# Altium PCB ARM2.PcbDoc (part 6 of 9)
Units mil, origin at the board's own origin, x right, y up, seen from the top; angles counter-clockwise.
Board outline 4700.79 x 3937.01 mil, 6 copper layers (Top Layer, GND02, ART03, ART04, PWR05, Bottom Layer); 697 components, 508 nets, 2326 pads, 1231 vias.
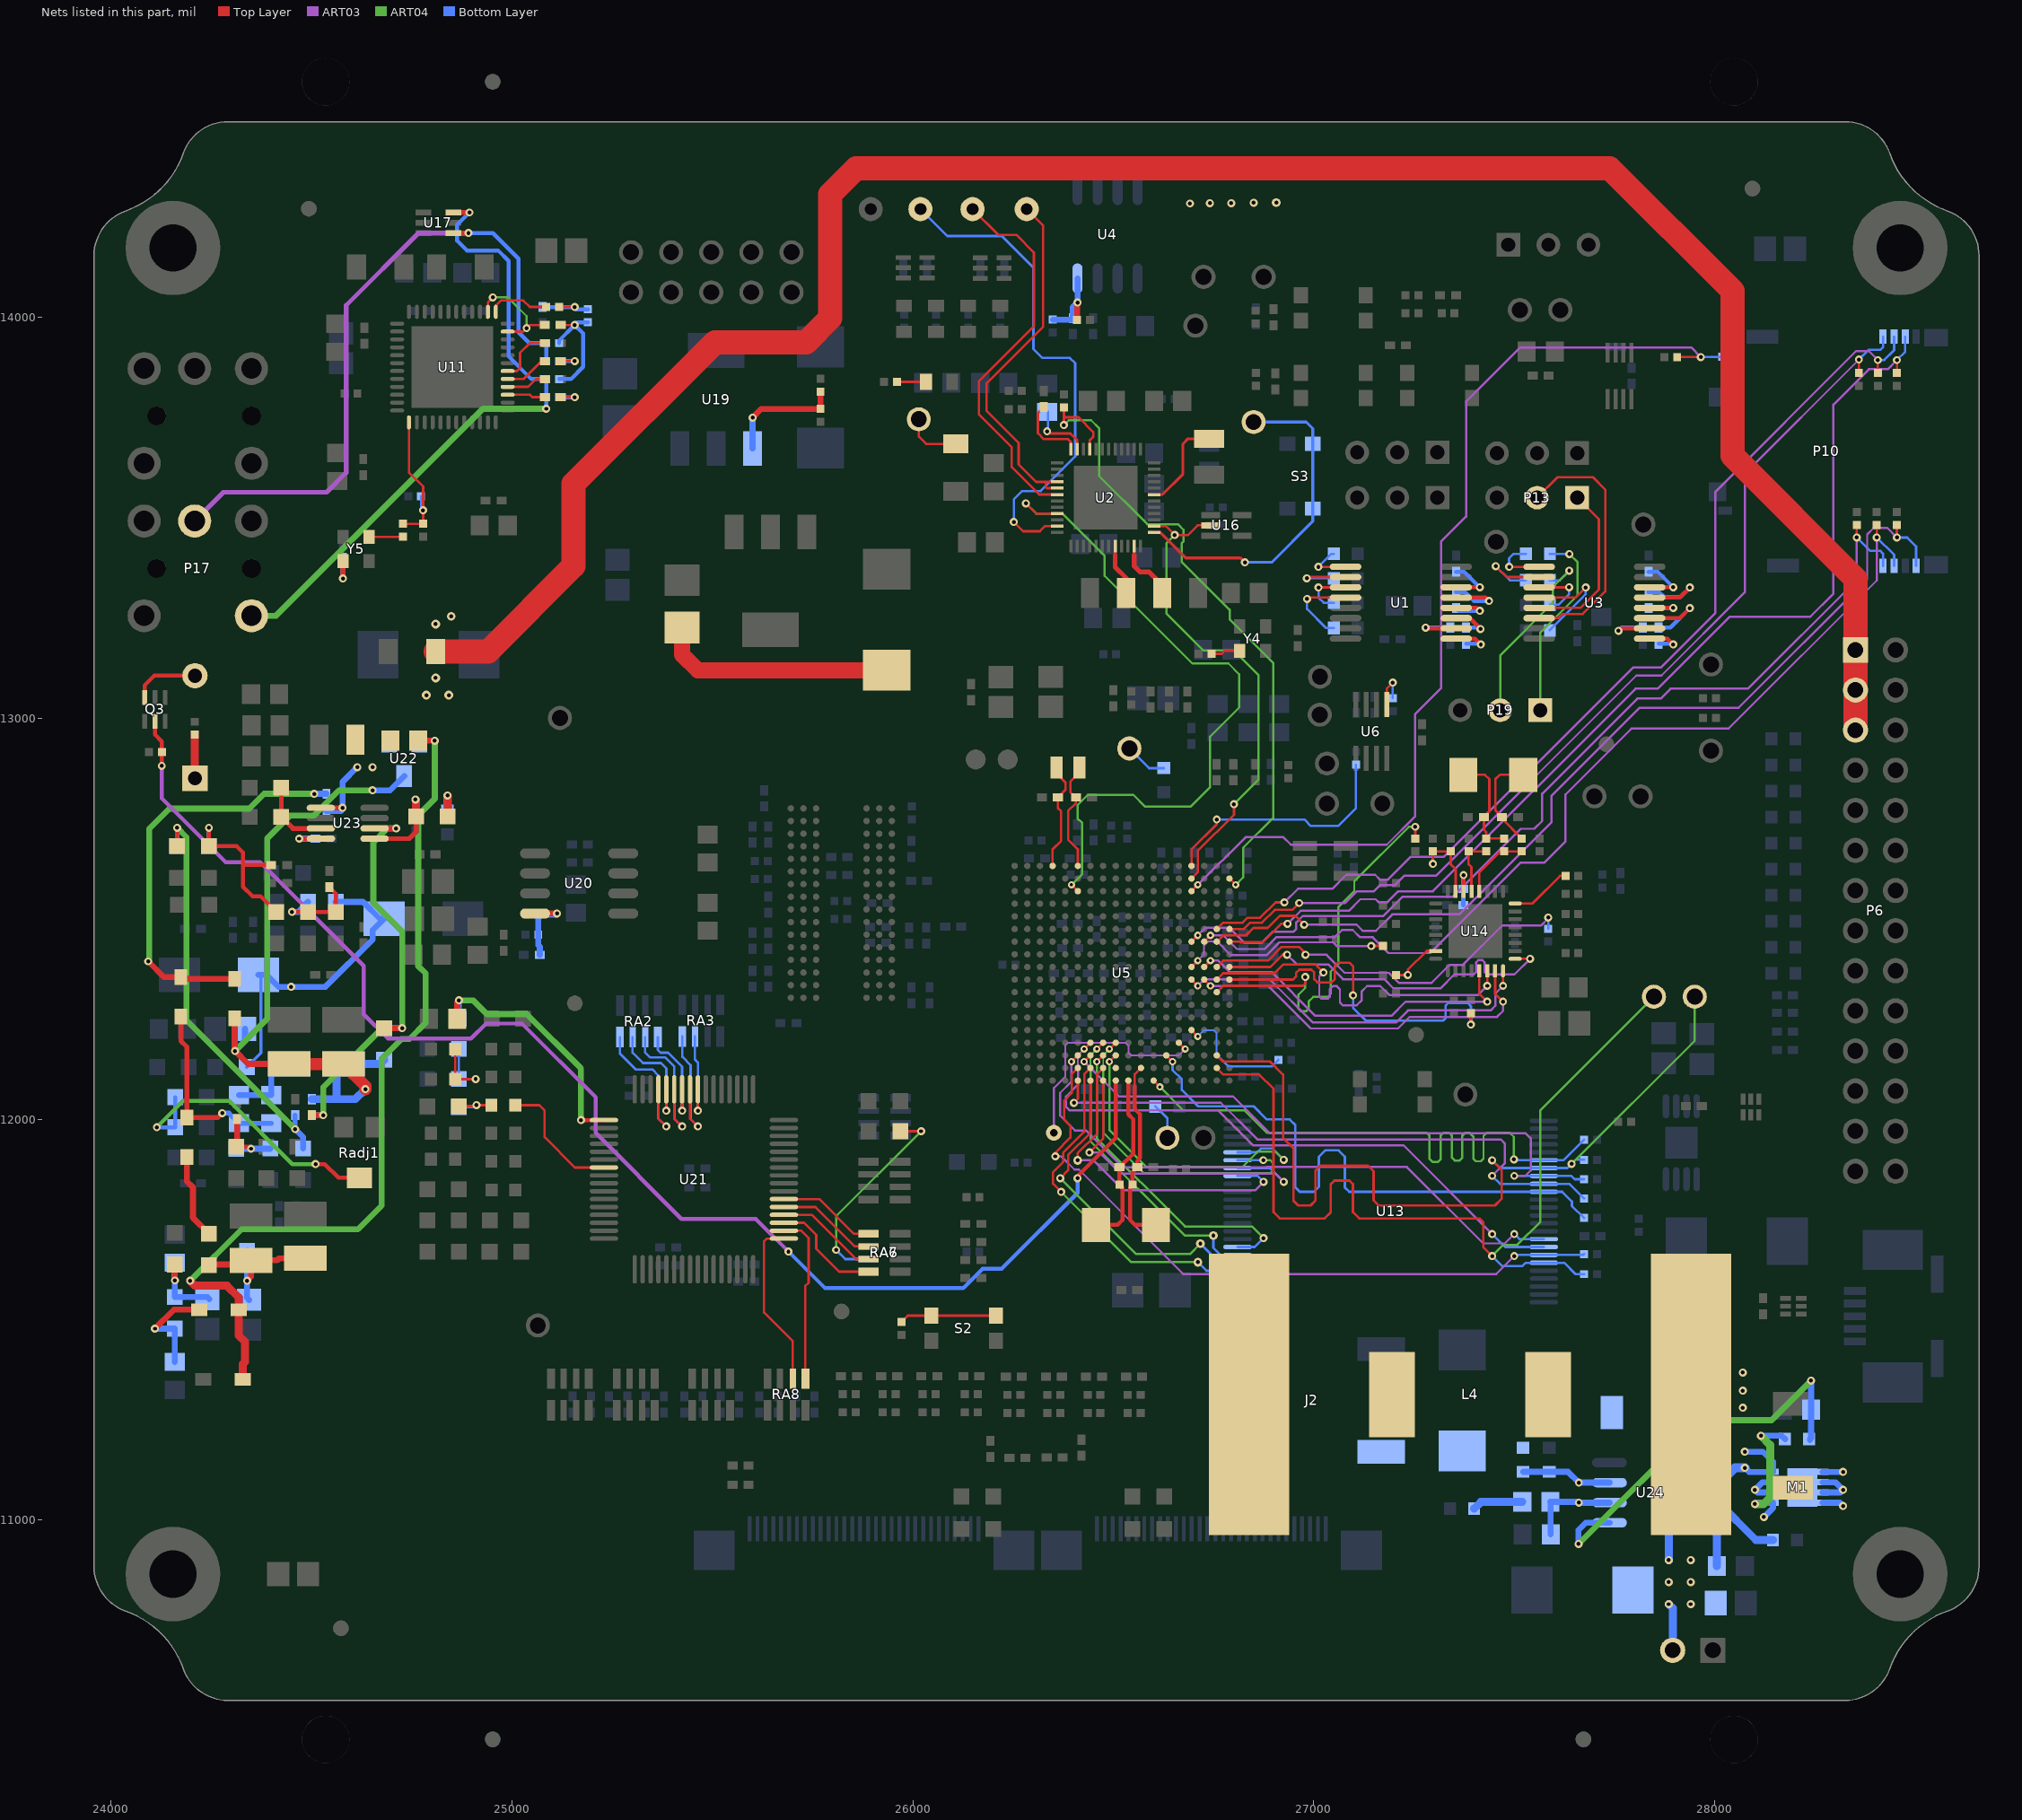
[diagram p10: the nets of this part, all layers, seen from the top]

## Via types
v1: diameter 20, hole 10, Top Layer to Bottom Layer, tented both sides, 871 vias
v2: diameter 18, hole 8, Top Layer to Bottom Layer, tented both sides, 273 vias
v3: diameter 22, hole 10, Top Layer to Bottom Layer, tented both sides, 64 vias
v4: diameter 20, hole 10, Top Layer to Bottom Layer, 18 vias
v5: diameter 22, hole 12, Top Layer to Bottom Layer, 4 vias
v6: diameter 39.37, hole 19.68, Top Layer to Bottom Layer, 1 vias

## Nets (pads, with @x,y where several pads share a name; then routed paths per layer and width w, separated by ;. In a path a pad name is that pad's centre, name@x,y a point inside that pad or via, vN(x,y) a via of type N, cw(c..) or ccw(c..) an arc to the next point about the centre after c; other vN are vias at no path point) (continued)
MII1_RXD3: R125.1 U5.L17 | length 986.3
  Top Layer w6: U5.L17@26758.2,12316.76 26773.94,12332.5 26972.88,12332.5 26979,12338.62 v1(26979,12354.73) ; R125.1@27253.11,12700.14 v1(27253.11,12729.32)
  ART04 w5.5: v1(26979,12354.73) 26979,12327.48 26961.79,12310.26 26961.79,12275.41 26967.58,12269.61 26981.66,12269.61 26987.16,12275.12 26987.16,12293.35 26998.82,12305.01 27034.82,12305.01 27042.34,12312.53 27042.34,12367.99 27061.12,12386.77 27061.12,12528.57 27101.12,12568.57 27101.12,12592.99 27237.46,12729.32 v1(27253.11,12729.32)
MII1_RXDV: R129.1 U5.J17 | length 983.4
  Top Layer w6: U5.J17@26758.2,12379.75 26773.94,12395.49 26885.87,12395.49 26920.05,12429.67 26963.33,12429.67 26979.26,12413.74 v1(26979.26,12410)
  ART03 w5.5: v1(26979.26,12410) 27032,12410 27077,12365 27187,12365 27212,12340 27294,12340 27339,12385 27372,12385 27469.7,12482.7 27566.7,12482.7 27585,12501 v1(27585,12503)
  Bottom Layer w6: R129.1@27585,12475.14 v1(27585,12503)
MII1_RXERR: R133.1 U5.J15 | length 547.3
  Top Layer w6: U5.J15@26695.21,12379.75 v2(26710.96,12395.5) ; v1(27143.54,12432) R133.1@27172.72,12432
  ART03 w4.4: v2(26710.96,12395.5) 26726.46,12411 26726.46,12432.92 26736.53,12442.99 26749.39,12442.99
  ART03 w5.5: 26749.39,12442.74 26759.4,12442.74 26792.81,12409.32 26882.69,12409.32 26914.47,12441.1 27048.15,12441.1 27057.25,12432 v1(27143.54,12432)
MII1_TXCLK: R134.1 U5.K18 | length 914.1
  Top Layer w6: U5.K18@26789.7,12348.25 26948.63,12348.25 26956,12355.62 26956,12364.57 26964.15,12372.73 26994.16,12372.73 27001,12365.89 27001,12349.28 27009.04,12341.25 27044.72,12341.25 27052.7,12349.23 27052.7,12382.63 27060.45,12390.37 27089.13,12390.37 27098,12381.5 v1(27098,12309) ; v1(27391.88,12236.06) R134.1@27391.88,12263.92
  Bottom Layer w6: v1(27098,12309) 27098,12277.67 27129.8,12245.87 27322.58,12245.87 27329,12252.29 27329,12283.55 27335.08,12289.63 27383.92,12289.63 27391.88,12281.67 v1(27391.88,12236.06)
MII1_TXD0: U5.K17 U14.22 | length 926.6
  Top Layer w6: U5.K17@26758.2,12348.25 26773.94,12363.99 26902.28,12363.99 26924.29,12386 27004,12386 v1(27024,12366) ; v1(27432.66,12332.56) U14.22@27432.66,12370
  ART03 w5.5: v1(27024,12366) 27013.85,12355.85 27013.85,12306.16 27019.61,12300.4 27034.66,12300.4 27039.75,12305.49 27039.75,12323.98 27047.4,12331.63 27057.6,12331.63 27065.25,12323.98 27065.25,12290.75 27072,12284 27107,12284 27120,12297 27120,12319 27133,12332 27166,12332 27188,12310 27410.1,12310 v1(27432.66,12332.56)
MII1_TXD1: U5.K16 U14.23 | length 922.1
  Top Layer w6: U5.K16@26726.7,12348.25 v2(26742.45,12332.51) ; U14.23@27452.36,12370 27452.36,12312.86 v1(27472.06,12293.16)
  ART03 w5.5: v2(26742.45,12332.51) 26886.49,12332.51 26992.71,12226.29 27210.29,12226.29 27239.24,12255.24 27457.3,12255.24 27472.06,12270 v1(27472.06,12293.16)
MII1_TXD2: U5.K15 U14.24 | length 928
  Top Layer w6: U5.K15@26695.21,12348.25 v2(26710.96,12332.51) ; v1(27472.06,12332.56) U14.24@27472.06,12370
  ART03 w5.5: v2(26710.96,12332.51) 26727.22,12348.78 26890.22,12348.78 26998,12241 27205,12241 27235.24,12271.24 27441.24,12271.24 27453,12283 27453,12313.5 v1(27472.06,12332.56)
MII1_TXD3: U5.J18 U14.25 | length 923.7
  Top Layer w6: U5.J18@26789.7,12379.75 26891.75,12379.75 26922,12410 v1(26933.72,12410) ; U14.25@27502.11,12400.05 v1(27539.55,12400.05)
  ART03 w5.5: v1(26933.72,12410) 26957.72,12386 27036,12386 27073,12349 27176,12349 27199,12326 27316,12326 27351,12361 27399.1,12361 27405.25,12367.15 27405.25,12391.26 27411.4,12397.41 27419.6,12397.41 27425.75,12391.26 27425.75,12367.15 27431.9,12361 27500.5,12361 v1(27539.55,12400.05)
MII1_TXEN: U5.J16 U14.21 | length 869
  Top Layer w6: U5.J16@26726.7,12379.75 v2(26742.45,12395.5) ; U14.21@27412.96,12370 27412.96,12312.86 v1(27432.66,12293.16)
  ART03 w5.5: v2(26742.45,12395.5) 26761.76,12395.5 26790.32,12366.94 26895.06,12366.94 27004,12258 27194,12258 27229.16,12293.16 v1(27432.66,12293.16)
MMC0_CD: P10.10 R157.1 U5.C15 | length 2508.7
  Top Layer w6: U5.C15@26695.21,12568.72 v2(26710.96,12584.47) ; R157.1@27906.27,13900.57 v1(27965.12,13900.57)
  ART03 w5.5: v2(26710.96,12584.47) 26829.88,12703.39 26924.31,12703.39 26943.12,12684.57 27182.12,12684.57 27253.12,12755.57 27253.12,13010.71 27318.12,13075.71 27318.12,13441.12 27380,13503 27380,13789.45 27515.12,13924.57 27941.12,13924.57 v1(27965.12,13900.57)
  Bottom Layer w6: v1(27965.12,13900.57) 28025.81,13900.57 P10.10@28026.37,13901.13
MMC0_CLKO: P10.5 R152.2 U5.G17 | length 2405.5
  Top Layer w6: U5.G17@26758.2,12442.74 26773.94,12458.48 26830.82,12458.48 26849.34,12477 26885.05,12477 26915.33,12507.28 26954.11,12507.28 v1(26976.14,12485.25) ; v1(28454.12,13450.57) R152.2@28454.12,13482.29
  ART03 w5.5: v1(26976.14,12485.25) 27106.45,12485.25 27122.12,12469.57 27155.12,12469.57 27196.12,12510.57 27363.01,12510.57 27592.56,12740.12 27592.56,12805.64 27813.12,13026.2 28059.58,13026.2 28380.12,13346.75 28380.12,13458.29 28396.41,13474.57 28430.12,13474.57 v1(28454.12,13450.57)
  Bottom Layer w6: v1(28454.12,13450.57) 28480.12,13450.57 28502.33,13428.37 P10.5@28502.33,13380.17
MMC0_CMD: P10.3 R151.2 U5.G18 | length 2644.9
  Top Layer w6: U5.G18@26789.7,12442.74 26815,12442.74 ; 26816.74,12441 26872.75,12441 26919.12,12487.37 v1(26934.78,12487.37) ; R151.2@28454.43,13861.42 v1(28454.43,13893.13)
  ART03 w5.5: v1(26934.78,12487.37) 26967.28,12519.87 27087.42,12519.87 27116.12,12548.57 27154.12,12548.57 27161.12,12541.57 27184.12,12541.57 27211.12,12568.57 27297.3,12568.57 27802.38,13073.66 27857.7,13073.66 28037.35,13253.3 28238.68,13253.3 28296.12,13310.75 28296.12,13781.91 28384.56,13870.35 28431.65,13870.35 v1(28454.43,13893.13)
  Bottom Layer w6: v1(28454.43,13893.13) 28474.76,13913.47 P10.3@28474.76,13951.61
MMC0_DAT0: P10.7 R153.2 U5.G16 | length 2422.1
  Top Layer w6: U5.G16@26726.7,12442.74 v2(26742.45,12458.49) ; v1(28404.12,13450.57) R153.2@28404.12,13482.29
  ART03 w5.5: v2(26742.45,12458.49) 26774.34,12458.49 26808.52,12424.31 26877.87,12424.31 26907.84,12454.28 27052.99,12454.28 27070.55,12471.84 27097.12,12471.84 27115.39,12453.57 27147.12,12453.57 27186.45,12414.25 27289.8,12414.25 27515.11,12639.56 27574.86,12639.56 27627.94,12692.64 27627.94,12809.84 27792.4,12974.3 28034.68,12974.3 28404.12,13343.75 v1(28404.12,13450.57)
  Bottom Layer w6: v1(28404.12,13450.57) 28447.21,13407.49 P10.7@28447.21,13380.17
MMC0_DAT1: P10.8 R154.2 U5.G15 | length 2362.7
  Top Layer w6: U5.G15@26695.21,12442.74 v2(26710.96,12458.49) ; v1(28354.12,13450.57) R154.2@28354.12,13482.29
  ART03 w5.5: v2(26710.96,12458.49) 26729.47,12477 26790.09,12477 26828.01,12439.08 26869.71,12439.08 26897.66,12467.04 26948.77,12467.04 26956.35,12474.62 26956.35,12490.56 26972.86,12507.07 27173.62,12507.07 27221.12,12554.57 27346.12,12554.57 27515.84,12724.29 27550.1,12724.29 27569.72,12743.91 27569.72,12811.75 27806.86,13048.89 27865.27,13048.89 27889.88,13073.5 28082.87,13073.5 28354.12,13344.75 v1(28354.12,13450.57)
  Bottom Layer w6: v1(28354.12,13450.57) 28387.12,13417.57 28412.12,13417.57 28419.65,13410.05 P10.8@28419.65,13380.17
MMC0_DAT2: P10.1 R150.2 U5.F18 | length 2463.3
  Top Layer w6: U5.F18@26789.7,12474.24 26825.81,12474.24 26841.56,12489.99 26870.99,12489.99 26902.96,12521.96 26946.73,12521.96 v1(26963.8,12539.03) ; R150.2@28359.43,13861.42 v1(28359.43,13894.27)
  ART03 w5.5: v1(26963.8,12539.03) 27078.58,12539.03 27108.12,12568.57 27150.12,12568.57 27165.12,12583.57 27202.12,12583.57 27226.12,12607.57 27305.55,12607.57 27804.31,13106.34 27867,13106.34 28074.8,13314.14 28074.8,13609.65 v1(28359.43,13894.27)
  Bottom Layer w6: v1(28359.43,13894.27) 28383.82,13918.67 28413.06,13918.67 28419.65,13925.25 P10.1@28419.65,13951.61
MMC0_DAT3: P10.2 R155.2 U5.F17 | length 2558.2
  Top Layer w6: U5.F17@26758.2,12474.24 26773.94,12489.98 26822.42,12489.98 26834.78,12502.34 26866.4,12502.34 26904.76,12540.7 v1(26926.77,12540.7) ; R155.2@28406.71,13861.42 v1(28406.71,13893.13)
  ART03 w5.5: v1(26926.77,12540.7) 26960.62,12574.55 27046.11,12574.55 27081.12,12609.57 27153.12,12609.57 27165.12,12597.57 27185.12,12597.57 27242.12,12654.57 27324.75,12654.57 27796.37,13126.19 27865.38,13126.19 28001.75,13262.56 28001.75,13564.68 28352.82,13915.75 28384.1,13915.75 v1(28406.71,13893.13)
  Bottom Layer w6: v1(28406.71,13893.13) 28422.65,13893.13 28447.21,13917.69 P10.2@28447.21,13951.61
MMC1_CLK: U5.U9
MMC1_CMD_BEEP: Q3.2 R34.1 U5.V9 | length 3561.1
  Top Layer w10: Q3.2@24110.19,12992.54 24110.19,12959.07 24127.33,12941.93 R34.1@24127.33,12915.07 v1(24127.33,12881.21) ; v1(26411,11852.62) 26411,11858.04 26506.23,11953.27 U5.V9@26506.23,12096.28
  ART03 w10: v1(24127.33,12881.21) 24127.33,12800.37 24286.7,12641 24372.7,12641 24631,12382.7 24631,12261.7 24691.7,12201 24898.55,12201 24936.12,12238.57 25025.43,12238.57 25209.12,12054.88 25209.12,11965.88 25423.43,11751.57 25608.43,11751.57 v1(25690,11670)
  Bottom Layer w10: v1(25690,11670) 25781.57,11578.43 26125.83,11578.43 26174.41,11627 26221.63,11627 26411,11816.37 v1(26411,11852.62)
MODE2: R113.1 R138.2 U14.15 | length 161
  Top Layer w6: R138.2@27205,12359.83 v1(27234.67,12359.83) 27234.67,12372.42 27282,12419.75 U14.15@27304.11,12419.75
  Bottom Layer w6: R113.1@27205,12359.83 v1(27234.67,12359.83)
NAND_ALE: U5.R7 U13.17 | length 1521.4
  Top Layer w6: v2(26427.49,12175.03) U5.R7@26443.24,12190.77
  ART03 w4.4: 26411.99,12136.59 26411.99,12159.53 v2(26427.49,12175.03)
  ART03 w5.5: 26411.99,12136.59 26411.99,12085.99 26382.48,12056.48 26382.48,12030.52 26391.42,12021.58 26762.06,12021.58 26848.61,11935.03 27223.59,11935.03 v1(27445,11713.62)
  Bottom Layer w6: v1(27445,11713.62) 27477.36,11681.26 U13.17@27573.78,11681.26
NAND_CLE: U5.T6 U13.16 | length 1522.2
  Top Layer w6: v2(26395.99,12143.54) U5.T6@26411.74,12159.28
  ART03 w5.5: v2(26395.99,12143.54) 26395.99,12093.99 26367.67,12065.67 26367.67,12008.79 26404.47,11972 26431.7,11972 26523.66,11880.04 26881.35,11880.04 26881.94,11880.62 27232.43,11880.62 27422.77,11690.28 27476.66,11690.28 v1(27500,11713.62)
  Bottom Layer w6: v1(27500,11713.62) 27512.69,11700.94 U13.16@27573.78,11700.94
NAND_CSN0: R29.1 U5.V6 U13.9 | length 1521.5
  Top Layer w6: v1(26402,12041) 26411.74,12050.74 U5.V6@26411.74,12096.28
  ART03 w5.5: v1(26402,12041) 26768.17,12041 26859.72,11949.45 27466.41,11949.45 27476.04,11939.82 27476.04,11889.66 v1(27445,11858.62)
  Bottom Layer w6: v1(27445,11858.62) 27464.88,11838.74 U13.9@27573.78,11838.74 27637.5,11838.74 R29.1@27673.86,11802.38
NAND_CSN3: R16.1 U5.T13 U13.10 | length 1509.7
  Top Layer w6: U5.T13@26632.22,12159.28 v2(26647.97,12143.54)
  Bottom Layer w6: v2(26647.97,12143.54) 26647.97,12122.66 26671,12099.62 26671,12072.62 26711.49,12032.14 26850.7,12032.14 26883.29,11999.54 26940.15,11999.54 26953.92,11985.77 26953.92,11830.3 26965.17,11819.05 27000.13,11819.05 27012.53,11831.45 27012.53,11906.12 27028.64,11922.23 27062.15,11922.23 27077.74,11906.63 27077.74,11829.6 27088.29,11819.05 U13.10@27573.78,11819.05 27619.58,11819.05 27644,11794.62 27644,11783.48 R16.1@27673.86,11753.62
NAND_D0: U5.U7 U13.29 | length 877.6
  Top Layer w6: v1(26369.89,11818.63) 26349.92,11838.6 26349.92,11867.93 26375.26,11893.26 26375.26,11915.94 26427.88,11968.57 26427.88,12112.42 U5.U7@26443.24,12127.78
  ART04 w5.5: v1(26369.89,11818.63) 26544.9,11643.62 v3(26711.17,11643.62)
  Bottom Layer w6: v3(26711.17,11643.62) 26732.59,11622.2 U13.29@26810,11622.2
NAND_D1: U5.V7 U13.30 | length 825.7
  Top Layer w6: v1(26368,11852.62) 26387.53,11872.15 26387.53,11910.2 26443.24,11965.92 U5.V7@26443.24,12096.28
  ART04 w5.5: v1(26368,11852.62) 26557,11663.62 26691.19,11663.62 v3(26717.28,11689.71)
  Bottom Layer w6: v3(26717.28,11689.71) 26765.1,11641.89 U13.30@26810,11641.89
NAND_D2: U5.R8 U13.31 | length 760.6
  Top Layer w6: v2(26458.99,12175.03) U5.R8@26474.74,12190.77
  ART04 w4.4: 26443.49,12129 26443.49,12159.53 v2(26458.99,12175.03)
  ART04 w5.5: 26443.49,12129 26443.49,11944.86 26678.37,11709.98 v3(26749.7,11709.98)
  Bottom Layer w6: v3(26749.7,11709.98) 26749.7,11679.47 26767.61,11661.57 U13.31@26810,11661.57
NAND_D3: U5.T8 U13.32 | length 806.7
  Top Layer w6: v2(26458.99,12143.54) U5.T8@26474.74,12159.28
  ART04 w5.5: v2(26458.99,12143.54) 26458.99,11952.37 26678.98,11732.38 26846.24,11732.38 v1(26875,11703.62)
  Bottom Layer w6: U13.32@26810,11681.26 26852.64,11681.26 v1(26875,11703.62)
NAND_D4: U5.U8 U13.41 | length 831.5
  Top Layer w6: v3(26411.06,11897.49) 26411.06,11915.22 26459.38,11963.55 26459.38,12112.42 U5.U8@26474.74,12127.78
  ART03 w5.5: v3(26411.06,11897.49) 26451.13,11897.49 26526,11822.62 26854,11822.62 v1(26875,11843.62)
  Bottom Layer w6: U13.41@26810,11858.42 26860.21,11858.42 v1(26875,11843.62)
NAND_D5: U5.V8 U13.42 | length 837.5
  Top Layer w6: v1(26440.56,11917.1) 26474.74,11951.29 U5.V8@26474.74,12096.28
  ART03 w5.5: v1(26440.56,11917.1) 26465.52,11917.1 26518,11864.62 26904,11864.62 v1(26925,11843.62)
  Bottom Layer w6: U13.42@26810,11878.11 26890.51,11878.11 v1(26925,11843.62)
NAND_D6: U5.R9 U13.43 | length 815.6
  Top Layer w6: v2(26490.48,12175.03) U5.R9@26506.23,12190.77
  ART04 w4.4: 26474.98,12133.62 26474.98,12159.53 v2(26490.48,12175.03)
  ART04 w5.5: 26474.98,12133.62 26474.98,11966.67 26576.71,11864.95 26891.62,11864.95 26898.24,11871.57 26898.24,11890.99 26891.44,11897.79 v1(26874,11897.79)
  Bottom Layer w6: U13.43@26810,11897.79 v1(26874,11897.79)
NAND_D7: U5.T9 U13.44 | length 819.8
  Top Layer w6: v2(26490.48,12143.54) U5.T9@26506.23,12159.28
  ART04 w5.5: v2(26490.48,12143.54) 26490.48,11973.4 26583.27,11880.61 26821.98,11880.61 26860,11918.62 26905,11918.62 v1(26925,11898.62)
  Bottom Layer w6: U13.44@26810,11917.48 26858.86,11917.48 26868,11926.62 26897,11926.62 v1(26925,11898.62)
NAND_OEN: R31.1 U5.T7 U13.8 | length 1518.7
  Top Layer w6: v2(26427.49,12143.54) U5.T7@26443.24,12159.28
  ART03 w5.5: v2(26427.49,12143.54) 26514.41,12056.62 26798.57,12056.62 26889.77,11965.42 27527.47,11965.42 27540.97,11951.92 27540.97,11872.18 27527.41,11858.62 v1(27500,11858.62)
  Bottom Layer w6: v1(27500,11858.62) 27500.21,11858.42 U13.8@27573.78,11858.42 27642.38,11858.42 27650.51,11850.29 R31.1@27673.86,11850.29
NAND_WAIT0: R13.1 TP15.1 U5.T17 U13.7 | length 2105.3
  Top Layer w6: U5.T17@26758.2,12159.28 26773.5,12143.98 26890.64,12143.98 26923.51,12111.12 26923.51,11953.67 26949.47,11927.71 26949.47,11796.8 26961.44,11784.84 26992.01,11784.84 27004.02,11796.85 27004.02,11871.66 27016.33,11883.97 27135.78,11883.97 27149.13,11870.62 27149.13,11797.58 27161.87,11784.84 27451.89,11784.84 27468.36,11801.31 27468.36,11874.26 v1(27445,11897.62)
  ART04 w5.5: v1(27643.12,11888.57) 27950.12,12195.57 TP15.1@27950.12,12305.57
  Bottom Layer w6: v1(27445,11897.62) 27464.51,11878.11 U13.7@27573.78,11878.11 27632.66,11878.11 v1(27643.12,11888.57) 27653.17,11898.62 R13.1@27673.86,11898.62
NAND_WAIT1: R15.1 U5.V12 U13.6 | length 1582.3
  Top Layer w6: U5.V12@26600.72,12096.28 v2(26616.47,12080.54)
  ART04 w5.5: v2(26616.47,12080.54) 26675.26,12021.75 26827.88,12021.75 26884,11965.62 27282.27,11965.62 27289.03,11958.87 27289.03,11901.01 27296.22,11893.82 27309.96,11893.82 27316.06,11899.92 27316.06,11958.65 27323.04,11965.62 27338.08,11965.62 27344.92,11958.79 27344.92,11903.62 27351.48,11897.06 27363.97,11897.06 27370.53,11903.62 27370.53,11958.96 27377.19,11965.62 27389.01,11965.62 27397.73,11956.91 27397.73,11902.04 27404.69,11895.08 27416.55,11895.08 27423.35,11901.88 27423.35,11958.17 27430.79,11965.62 27489.42,11965.62 27499,11956.05 v1(27499,11899.62)
  Bottom Layer w6: v1(27499,11899.62) 27500.83,11897.79 U13.6@27573.78,11897.79 27623.02,11897.79 R15.1@27673.86,11948.62
NAND_WEN: R30.1 U5.U6 U13.18 | length 1717.1
  Top Layer w6: v1(26355.43,11907.33) 26355.43,11916.51 26393.06,11954.14 26393.06,11983.41 26377.89,11998.57 26377.89,12046.34 26396.38,12064.83 26396.38,12112.42 U5.U6@26411.74,12127.78
  ART03 w5.5: v1(26355.43,11907.33) 26370.34,11907.33 26403.4,11874.27 26414.45,11874.27 26675.1,11613.62 27455,11613.62 v1(27500,11658.62)
  Bottom Layer w6: v1(27500,11658.62) 27502.94,11661.57 U13.18@27573.78,11661.57 27671.8,11661.57 R30.1@27673.86,11663.62
NAND_WPN: R2.1 TP17.1 U5.U17 U13.19 | length 2347.2
  Top Layer w5.5: U5.U17@26758.2,12127.78 26774.65,12111.33 26799.67,12111.33
  Top Layer w6: 26799.67,12111.33 26864.19,12111.33 26899.63,12075.89 26899.63,11768.12 26915.17,11752.57 27027.2,11752.57 27042.37,11767.74 27042.37,11837.86 27051.47,11846.96 27089.08,11846.96 27097.57,11838.47 27097.57,11768.35 27113.34,11752.57 27413.75,11752.57 27423.09,11743.23 27423.09,11680.53 v1(27445,11658.62)
  ART04 w5.5: v1(27445,11658.62) 27473,11686.62 27507.63,11686.62 27565.38,11744.37 27565.38,12022.61 TP17.1@27848.34,12305.57
  Bottom Layer w6: v1(27445,11658.62) 27470,11633.62 27520,11633.62 27528.27,11641.89 U13.19@27573.78,11641.89 27624.73,11641.89 27653,11613.62 R2.1@27673.86,11613.62
NetC19_1: C19.1 R10.1 R11.2 U4.4 | length 199.7
  Top Layer w6: v1@26409.77,14035.64 v1(26410.92,14036.78)
  Top Layer w15: R11.2@26409.77,13992.88 v1@26409.77,14035.64
  Bottom Layer w15: R10.1@26349.54,13994.02 26395.68,13994.02 C19.1@26399.54,13997.88 26399.54,14025.41 v1(26410.92,14036.78) U4.4@26410.92,14096.88
NetC128_1: C128.1 U1.2 | length 138
  Top Layer w10: v1(27279,13226) 27280.99,13224.01 U1.2@27355,13224.01
  Bottom Layer w10: v1(27279,13226) C128.1@27340.2,13226
NetC129_1: C129.1 U1.6 | length 134.1
  Top Layer w10: U1.6@27355,13326.37 v1(27413.97,13326.37)
  Bottom Layer w10: C129.1@27355,13365.4 27374.93,13365.4 v1(27413.97,13326.37)
NetC130_1: C130.1 U1.1 | length 104.9
  Top Layer w10: U1.1@27355,13198.42 27402.22,13198.42 v1(27416.63,13184.01)
  Bottom Layer w10: C130.1@27380.2,13186 27414.64,13186 v1(27416.63,13184.01)
NetC130_2: C130.2 U1.3 | length 98.6
  Top Layer w10: U1.3@27355,13249.6 27389.02,13249.6 v1(27416,13222.62)
  Bottom Layer w10: C130.2@27380.2,13226 v1@27406.67,13226
NetC144_1: C144.1 U1.4 | length 124.2
  Top Layer w10: U1.4@27355,13275.19 27406.43,13275.19 v1(27414,13267.62)
  Bottom Layer w10: C144.1@27355,13275 27362.38,13267.62 v1(27414,13267.62)
NetC144_2: C144.2 U1.5 | length 176.6
  Top Layer w10: U1.5@27355,13300.78 27428.84,13300.78 v1(27437,13292.62)
  Bottom Layer w10: C144.2@27355,13315 27376.84,13315 27399.22,13292.62 v1(27437,13292.62)
NetC147_1: C147.1 C199.1 FB17.2 L4.1 P9.2 U24.8 | length 633.9
  Top Layer w6: L4.1@26838.82,11313.62 L4.1@26838.82,11514.86
  Bottom Layer w20: v1(27885.12,10790.57) 27895.12,10780.57 P9.2@27895.12,10675.57 ; v1(27885.12,10900.57) 27885.12,10993.62 U24.8@27942.36,10993.62 27992.14,10993.62 28005.12,10980.64 C199.1@28005.12,10885.57
  other v1: 27940.12,10790.57 27885.12,10845.57 27940.12,10845.57 27940.12,10900.57
NetC149_1: C149.1 D6.2 J2.2 R41.1
NetC158_1: C158.1 U3.2 | length 143.7
  Top Layer w10: v1(27760,13218) 27766.01,13224.01 U3.2@27837.66,13224.01
  Bottom Layer w10: v1(27760,13218) 27768,13226 C158.1@27820.2,13226
NetC174_1: C174.1 U3.6 | length 136.8
  Top Layer w10: U3.6@27837.66,13326.37 v1(27896.63,13326.37)
  Bottom Layer w10: C174.1@27835,13365.4 27857.6,13365.4 v1(27896.63,13326.37)
NetC175_1: C175.1 U3.1 | length 102.2
  Top Layer w10: U3.1@27837.66,13198.42 27882.22,13198.42 v1(27896.63,13184.01)
  Bottom Layer w10: C175.1@27860.2,13186 27894.64,13186 v1(27896.63,13184.01)
NetC175_2: C175.2 U3.3 | length 208.9
  Top Layer w10: U3.3@27837.66,13249.6 27912.94,13249.6 v1(27938.08,13274.74)
  Bottom Layer w10: C175.2@27860.2,13226 27889.34,13226 v1(27938.08,13274.74)
NetC176_1: C176.1 U3.4 | length 120.7
  Top Layer w10: U3.4@27837.66,13275.19 v1(27896.63,13275.19)
  Bottom Layer w10: C176.1@27835,13275 27896.44,13275 v1(27896.63,13275.19)
NetC176_2: C176.2 U3.5 | length 229.2
  Top Layer w10: U3.5@27837.66,13300.78 27912.94,13300.78 v1(27938.08,13325.92)
  Bottom Layer w10: C176.2@27835,13315 27861,13315 27874,13302 27914.16,13302 v1(27938.08,13325.92)
NetC179_1: C179.1 U11.11 U11.14 | length 273.7
  Top Layer w6: U11.14@24940.58,14013.42 24940.58,14037.1 v1(24953,14049.52) ; U11.11@24989.8,13964.2 25028.58,13964.2 v1(25037,13972.62) 25045,13980.62 C179.1@25082,13980.62
  ART04 w5.5: v1(24953,14049.52) 24990.17,14049.52 25037,14002.7 v1(25037,13972.62)
NetC179_2: C179.2 R105.2 R106.2 R107.2 | length 317.7
  Top Layer w6: C179.2@25122,13980.62 v1(25157,13980.62)
  Bottom Layer w10: R107.2@25118.14,13845.62 25147.62,13845.62 25178,13876 25178,13959.62 v1(25157,13980.62) ; R106.2@25118.14,13935.62 25118.14,13941.76 v1(25157,13980.62) ; R105.2@25190,13987.48 25163.86,13987.48 v1(25157,13980.62)
NetC182_1: C182.1 R104.2 R105.1 | length 154.3
  Top Layer w6: R104.2@25118.14,14025.62 v1(25157,14025.62)
  Bottom Layer w10: C182.1@25077,14025.62 v1(25157,14025.62) 25162.86,14019.76 R105.1@25190,14019.76
NetC183_1: C183.1 U11.3 | length 94.7
  Top Layer w6: U11.3@24989.8,13806.72 25045.28,13806.72 25051.38,13800.62 C183.1@25082,13800.62
NetC183_2: C183.2 R108.1 | length 73.9
  Top Layer w6: C183.2@25122,13800.62 v1(25157,13800.62)
  Bottom Layer w10: R108.1@25118.14,13800.62 v1(25157,13800.62)
NetC184_1: C184.1 U11.5 | length 110.6
  Top Layer w6: U11.5@24989.8,13846.09 25029.47,13846.09 25074,13890.62 C184.1@25082,13890.62
NetC184_2: C184.2 R109.1 | length 73.9
  Top Layer w6: C184.2@25122,13890.62 v1(25157,13890.62)
  Bottom Layer w10: R109.1@25118.14,13890.62 v1(25157,13890.62)
NetC193_1: C193.1 U11.6 | length 144.9
  Top Layer w6: U11.6@24990.96,13864.62 U11.6@24989.8,13865.78 25013,13865.78 25021,13873.78 25021,13911.62 25045,13935.62 C193.1@25082,13935.62
NetC194_1: C194.1 U11.4 | length 100.2
  Top Layer w6: U11.4@24989.8,13826.41 25040.79,13826.41 25060,13845.62 C194.1@25082,13845.62
NetC195_2: C195.2 C196.2 | length 593.6
  Top Layer w40: C195.2@25425,13225.94 25425,13158.7 25464.11,13119.59 C196.2@25935.12,13119.59
NetC201_1: C201.1 R149.1 R161.2 U20.4 | length 204.7
  Top Layer w15: U20.4@25058,12513 v1(25113,12513)
  Bottom Layer w15: C201.1@25070,12410 25070,12430 25066.14,12433.86 R149.1@25066.14,12460 R161.2@25066.14,12510 25110,12510 v1(25113,12513)
NetC203_1: C203.1 C281.1 U24.2 | length 229.8
  Bottom Layer w6: C203.1@27590.12,11045.57 C203.1@27590.97,11044.72
  Bottom Layer w15: C203.1@27590.12,11045.57 27659.22,11045.57 27661.17,11043.62 U24.2@27737.64,11043.62 ; C281.1@27590.97,10964.4 C203.1@27590.97,11044.72
  other v1: 27661.12,11043.57
NetC203_2: C203.2 R175.1 | length 127.3
  Bottom Layer w20: R175.1@27399.84,11028.62 27416.79,11045.57 C203.2@27520.12,11045.57
NetC241_1: C241.1 C259.1 L5.2 U22.1 U22.2 U23.5 | length 212.9
  Top Layer w12: U23.5@24524.07,12776.39 v1(24577.94,12776.39)
  Bottom Layer w15: v1(24577.94,12776.39) 24577.94,12840.94 v1(24615,12878)
  Bottom Layer w20: C241.1@24537.94,12771.39 24572.94,12771.39 v1(24577.94,12776.39)
  other v1: 24653,12878
NetC241_2: C241.2 D7.2 D8.1 | length 1132.2
  Top Layer w15: v1(24093.58,12393.58) 24132.95,12354.21 D8.1@24175,12354.21 24179,12350.21 D7.2@24309,12350.21
  ART04 w15: v1(24093.58,12393.58) 24095.61,12395.61 24095.61,12530 ; 24095.61,12499.39 24095.61,12530 ; 24095.61,12698.61 24095.61,12640 ; v1(24507.61,12811.39) 24382.39,12811.39 24345.37,12774.37 24146.37,12774.37 24095.61,12723.61 24095.61,12640 ; 24095.61,12530 24095.61,12640
  Bottom Layer w15: v1(24507.61,12811.39) C241.2@24537.94,12811.39
NetC245_2: C245.2 C246.2 FB14.1 R200.1 R201.2 | length 421
  Top Layer w15: R200.1@24250,11637.63 24340.63,11637.63 C246.2@24350,11647 ; v1(24340,11597) 24350,11607 C246.2@24350,11647 ; C246.2@24350,11648.07 C246.2@24350,11647 ; C245.2@24485,11653.07 24420,11653.07 24415,11648.07 24351.07,11648.07 C246.2@24350,11647
  Bottom Layer w15: R201.2@24340,11671.69 v1(24340,11597) 24340,11554.4 FB14.1@24345,11549.4
NetC247_1: C247.1 C248.1 C251.2 C252.2 C253.2 C254.2 C255.2 D7.1 FB15.1 R212.2 U22.3 | length 2152.7
  Top Layer w15: D7.1@24309,12251.79 24309,12171 v1(24310,12170) 24342.24,12137.76 C251.2@24445,12137.76
  Top Layer w30: C251.2@24445,12137.76 C252.2@24580,12137.76 24635,12082.76 v1(24635,12075)
  ART04 w15: v1(24310,12170) 24390,12250 24390,12700 24447,12757 24506,12757 24569,12820 v1(24653,12820)
  Bottom Layer w15: v1(24310,12170) 24334.8,12194.8 FB15.1@24334.8,12225 ; C248.1@24320,12060 C247.1@24400,12060 24400,12112 C254.2@24425.76,12137.76 ; v1(24653,12820) 24696.31,12820 U22.3@24732,12855.69
  Bottom Layer w20: C254.2@24425.76,12137.76 C253.2@24580,12137.76 ; C255.2@24502,12050 24563.6,12050 ; v1(24635,12075) 24610,12050 24563.6,12050 ; R212.2@24681.81,12148.23 24671.34,12137.76 C253.2@24580,12137.76 ; 24563.6,12050 24563.6,12121.36 C253.2@24580,12137.76
NetC247_2: C247.2 C248.2 D8.2 D9.1 | length 482.6
  Top Layer w12: D8.2@24175,12255.79 24175,12195 24190,12180 D9.1@24190,12004.21 24267.21,12004.21 v1(24278,12015)
  Bottom Layer w12: v1(24278,12015) 24295,12015 C248.2@24320,11990 C247.2@24400,11990
NetC249_2: C249.2 U23.8 | length 93.9
  Top Layer w12: v1(24470.2,12699.61) U23.8@24524.07,12699.61
  Bottom Layer w15: v1(24470.2,12699.61) C249.2@24510.2,12699.61
NetC255_1: C255.1 C258.2 R212.1 R214.2 U23.2 | length 1092.4
  Top Layer w12: U23.2@24657.93,12725.2 v1(24711.8,12725.2)
  Top Layer w15: C258.2@24502,12010 v1(24530,12010) ; R214.2@24681.81,12226.97 v1(24726.97,12226.97)
  ART04 w15: v1(24530,12010) 24530,12080 24676.97,12226.97 v1(24726.97,12226.97) 24726.97,12468.03 24655,12540 24655,12690.2 24690,12725.2 v1(24711.8,12725.2)
  Bottom Layer w15: C255.1@24502,12010 v1(24530,12010) ; R212.1@24681.81,12226.97 v1(24726.97,12226.97)
NetC256_1: C256.1 R211.1 U23.1 | length 229.5
  Top Layer w12: U23.1@24657.93,12699.61 24744.61,12699.61 24761.63,12716.63 R211.1@24761.63,12755
  Top Layer w20: v1(24760,12797.37) 24761.63,12795.74 R211.1@24761.63,12755
  Bottom Layer w18: C256.1@24760,12760 v1(24760,12797.37)
NetC257_1: C257.1 R211.2 | length 89.7
  Top Layer w20: R211.2@24840.37,12755 v1@24840.37,12807.29
  Bottom Layer w18: C257.1@24840,12769.92 v1(24840,12807.29)
NetC259_2: C259.2 D10.1 D11.2 | length 2189.1
  Top Layer w15: C259.2@24767,12944 v1(24808,12944)
  Top Layer w20: v1(24198,11597) 24210,11585 24290,11585 24319.21,11555.79 D11.2@24319.21,11525 24319.21,11460.79 24335,11445 24335,11395 24329.21,11389.21 D10.1@24329.21,11351.5
  ART04 w15: v1(24198,11597) 24326.57,11725.57 24616.5,11725.57 24675.5,11784.57 24675.5,12150.5 24725,12200 24745,12200 24785.5,12240.5 24785.5,12363.32 24767,12381.82 24767,12758 24808,12799 v1(24808,12944)
NetC260_2: C260.2 D11.1 R216.1 | length 263
  Top Layer w15: v1(24110,11477.63) 24157.37,11525 D11.1@24220.79,11525
  Bottom Layer w15: v1(24110,11477.63) R216.1@24160,11477.63 C260.2@24160,11395
NetC261_2: C261.2 FB16.1 R216.2 R217.2 | length 213.3
  Top Layer w15: v1(24160,11598) R217.2@24160,11637.63
  Bottom Layer w15: C261.2@24160,11642 v1(24160,11598) R216.2@24160,11556.37 24241.03,11556.37 FB16.1@24246,11551.4
NetC262_1: C262.1 C263.1 R223.2 R224.1 | length 794.8
  Bottom Layer w8: R223.2@24339.37,12130 24374.74,12165.37 24374.74,12353.69 C262.1@24368.43,12360
  Bottom Layer w15: C262.1@24368.43,12360 24388.17,12360 24418.17,12330 v1(24450,12330) 24535,12330 24653.5,12448.5 24653.5,12471.92 C263.1@24681.57,12500 24671,12500 24629.26,12541.74 R224.1@24561,12541.74
NetC265_1: C265.1 R218.1 R225.2 R226.1 | length 228.3
  Top Layer w10: v1(24451.91,12516.74) R226.1@24491.91,12516.74 R225.2@24561,12516.74 24561,12563 C265.1@24545,12579
  Bottom Layer w15: v1(24451.91,12516.74) 24466.91,12516.74 R218.1@24491.91,12541.74
NetC269_1: C269.1 R221.1 R229.2 R230.1 | length 447.9
  Top Layer w10: v1(24244.72,12726.63) R221.1@24244.72,12680.74 24314.26,12680.74 24330,12665 24330,12634 ; C269.1@24400,12634 24330,12634 ; R229.2@24412.81,12516.74 24373.36,12556.2 24353.36,12556.2 24330,12579.56 24330,12634
  Bottom Layer w10: R230.1@24244.72,12680.74 v1(24244.72,12726.63)
NetC272_1: C272.1 R219.1 R232.2 R233.1 | length 1056.9
  Top Layer w10: R232.2@24165.63,12680.74 v1(24165.63,12726.63)
  ART04 w15: v1(24165.63,12726.63) 24188.76,12703.5 24188.76,12246.24 v1(24460,11975)
  Bottom Layer w10: R219.1@24165.63,12680.74 v1(24165.63,12726.63)
  Bottom Layer w12: v1(24460,11975) C272.1@24460,12010
  Bottom Layer w15: v1(24460,11975) 24480,11955 R233.1@24480,11926.74
NetC276_1: C276.1 R220.2 R236.2 R237.1 | length 190.9
  Top Layer w10: R237.1@24313,11931.37 24345,11931.37 v1(24350,11926.37)
  Top Layer w15: R237.1@24315,11933.37 C276.1@24315,12000
  Bottom Layer w15: R220.2@24313,11926.37 v1(24350,11926.37) 24397.63,11926.37 R236.2@24398,11926.74
NetC282_1: C282.1 R168.2 U24.1 | length 1018
  ART04 w15: v1(27660.12,10940.57) 27969.12,11249.57 28141.62,11249.57 v1(28240.12,11348.07)
  Bottom Layer w15: v1(27660.12,10940.57) 27660.12,10975.57 27678.17,10993.62 U24.1@27737.64,10993.62 ; R168.2@28237.55,11199.88 28237.55,11202.38 28240.12,11204.96 C282.1@28240.12,11275.57 v1(28240.12,11348.07)
NetD6_1: D6.1 L4.2 M1.8 | length 292.4
  Top Layer w7: L4.2@27941.18,11313.62 L4.2@28015.67,11313.62
  Bottom Layer w7: v1@28319.79,11075.91 v1(28320.12,11075.57)
  Bottom Layer w15: M1.8@28268.99,11043.47 28312.23,11043.47 v1(28320.12,11035.57) ; M1.8@28268.99,11069.06 28312.95,11069.06 28319.79,11075.91 28301.05,11094.65 M1.8@28268.99,11094.65 ; M1.8@28268.99,11120.24 v1(28319.79,11120.24)
  other v1: 28070.12,11280.57 28070.12,11323.07 28070.12,11368.07
NetD9_2: D9.2 R200.2 | length 214.2
  Top Layer w15: D9.2@24190,11905.79 24190,11845 24205,11830 24205,11754.37 R200.2@24245,11714.37
NetLS1_1: LS1.1 R32.2 | length 108.8
  Top Layer w20: LS1.1@24210,12850.05 R32.2@24210,12958.86
NetLS1_2: LS1.2 Q3.6 | length 165.8
  Top Layer w10: Q3.6@24084.6,13051.6 24084.6,13082.2 24108.35,13105.95 LS1.2@24210,13105.95
NetM1_2: M1.2 R168.1 R176.2 | length 462.7
  ART04 w20: v1(28100.12,11040.57) 28122.23,11040.57 28138.12,11056.47 28138.12,11187.57 v1(28115.12,11210.57)
  Bottom Layer w15: v1(28100.12,11040.57) 28103.02,11043.47 M1.2@28144.97,11043.47 28144.97,11030.42 v1(28122.62,11008.07) ; v1(28115.12,11210.57) 28167.01,11210.57 R168.1@28175.2,11202.38 ; M1.2@28144.97,11069.06 28106.64,11069.06 v1(28100.12,11075.57) 28119.2,11094.65 M1.2@28144.97,11094.65
NetM1_4: M1.4 U24.6 | length 327.8
  Bottom Layer w15: v1(28075.12,11130.57) 28085.46,11120.24 M1.4@28144.97,11120.24 28144.97,11145.72 28120.12,11170.57 v1(28075.12,11170.57)
  Bottom Layer w23: U24.6@27942.36,11093.62 28013.17,11093.62 28050.12,11130.57 v1(28075.12,11130.57)
NetP17_2: P17.2 R107.1 R108.2 U17.3 | length 1650.2
  Top Layer w12: U17.3@24854.4,14261.21 v1(24894.41,14261.21)
  ART04 w15: P17.2@24351,13255.51 24412.06,13255.51 24928.17,13771.62 v1(25086,13771.62)
  Bottom Layer w10: v1(24894.41,14261.21) 24864,14230.8 24864,14190.62 24888,14166.62 24966,14166.62 24992,14140.62 24992,13902.62 25049,13845.62 R107.1@25085.86,13845.62 R108.2@25085.86,13800.62 25086,13800.48 v1(25086,13771.62)
NetP17_4: P17.4 R106.1 R109.2 U17.1 | length 1722.4
  Top Layer w12: U17.1@24854.4,14210.03 v1(24892.12,14210.03)
  ART03 w12: P17.4@24209.27,13491.73 24280.96,13563.42 24538.28,13563.42 24587.12,13612.27 24587.12,14029.57 24767.58,14210.03 v1(24892.12,14210.03)
  Bottom Layer w10: v1(24892.12,14210.03) 24953.04,14210.03 25017,14146.07 25017,13962.62 25044,13935.62 R106.1@25085.86,13935.62 R109.2@25085.86,13890.62
NetR21_1: R21.1 U6.5 | length 99.4
  Top Layer w6: U6.5@27182,13034 27182,13073.66 v1(27197,13088.66)
  Bottom Layer w6: R21.1@27197,13050.14 v1(27197,13088.66)
NetR33_2: R33.2 U1.12 | length 208.6
  Top Layer w6: v1(26983.32,13297.32) 26986.78,13300.78 U1.12@27079.41,13300.78
  Bottom Layer w6: v1(26983.32,13297.32) 26983.32,13272.68 27031,13225 R33.2@27050.01,13225
NetR35_2: R35.2 R36.1 U19.1 | length 297.7
  Top Layer w15: v1(25600.55,13749.45) 25622.37,13771.27 R35.2@25770,13771.27 R36.1@25770,13813.98
  Bottom Layer w15: U19.1@25600.55,13672.95 v1(25600.55,13749.45)
NetR39_2: R39.2 R41.2 U24.3 | length 226.6
  Bottom Layer w6: v1(27661.12,11093.57) v1@27661.17,11093.62
  Bottom Layer w15: R41.2@27522.25,11120.65 R39.2@27587.25,11120.65 27634.05,11120.65 v1(27661.12,11093.57) ; v1@27661.17,11093.62 U24.3@27737.64,11093.62
NetR42_2: R42.2 U3.12 | length 269.9
  Top Layer w6: U3.12@27562.07,13300.78 27653.01,13300.78 v1(27678.15,13325.92)
  Bottom Layer w6: R42.2@27588.56,13219.62 27678.15,13309.21 v1(27678.15,13325.92)
NetR43_1: R43.1 Y5.1 | length 96.7
  Top Layer w12: v1(24579,13348.62) Y5.1@24579,13391.48
  Bottom Layer w12: v1(24579,13348.62) R43.1@24579,13402.48
NetR75_2: R75.2 S2.1 S2.3 | length 242.1
  Top Layer w6: R75.2@25972,11494.76 25987.36,11510.12 S2.3@26046.29,11510.12 S2.1@26207.71,11510.12
NetR101_1: R101.1 R102.2 R103.2 U11.37 | length 354.7
  Top Layer w6: R101.1@24729,13484.76 R103.2@24779,13484.76 v1(24779,13518.62) 24779,13577.62 24743.73,13612.89 U11.37@24743.73,13737.82
  Bottom Layer w6: R102.2@24774,13553.62 24774,13523.62 v1(24779,13518.62)
NetR101_2: R101.2 Y5.3 | length 85
  Top Layer w6: Y5.3@24644,13452.48 R101.2@24729,13452.48
NetR104_1: R104.1 U11.13 | length 153
  Top Layer w6: U11.13@24960.27,14013.42 24960.27,14028.89 24973,14041.62 25029,14041.62 25045,14025.62 R104.1@25085.86,14025.62
NetR159_2: R159.2 U5.P15 | length 304.5
  Top Layer w6: U5.P15@26695.21,12222.27 v2(26710.96,12206.53)
  Bottom Layer w4.4: v2(26710.96,12206.53) 26726.46,12222.03 26750.6,12222.03 26757.95,12214.68 26757.95,12161.68
  Bottom Layer w6: 26757.95,12161.68 26788.01,12131.61 26895.37,12131.61 R159.2@26911.57,12147.82
NetR162_2: R162.2 R172.1 Radj1.3 | length 732.5
  Top Layer w10: v1(24511,11888) 24533.8,11888 24567.82,11853.98 Radj1.3@24620,11853.98
  ART04 w10: v1(24115,11980) 24181,12046 24295,12046 24453,11888 v1(24511,11888)
  Bottom Layer w10: v1(24115,11980) R172.1@24160.63,11980 R162.2@24160.63,12055
NetR167_1: R167.1 Y4.3 | length 72.9
  Top Layer w6: R167.1@26745.2,13160.61 26770.63,13160.61 26778.02,13168 Y4.3@26815,13168
NetR173_2: R173.2 U24.7 | length 241.4
  Bottom Layer w20: U24.7@27942.36,11043.62 28009.58,11043.62 28102.62,10950.57 R173.2@28145.2,10950.57
NetR189_2: R189.2 RA6.6 | length 526.1
  Top Layer w6: R189.2@25968.74,11970 v1(26021,11970)
  ART04 w5.5: v1(25809,11674) 25809,11758 v1(26021,11970)
  Bottom Layer w6: v1(25809,11674) 25831.75,11651.25 RA6.6@25889.63,11651.25
NetR192_1: R192.1 R194.2 R196.1 R199.1 | length 242.7
  Top Layer w6: R192.1@24858.92,12175 R196.1@24858.92,12100 v1(24910,12100)
  Bottom Layer w6: R194.2@24868.37,12175 R199.1@24868.37,12100 v1(24910,12100)
NetR193_2: R193.2 R195.1 R197.1 R198.1 | length 164.5
  Top Layer w6: R198.1@24868.37,12032.5 24909.5,12032.5 v1(24912,12035) R195.1@24949.08,12035
  Bottom Layer w6: R193.2@24868.37,12030 24907,12030 v1(24912,12035) R197.1@24949.08,12035
NetR213_2: R213.2 R215.2 U23.7 | length 183.6
  Top Layer w12: R215.2@24425.37,12827 R213.2@24425.37,12754 24454.17,12725.2 U23.7@24524.07,12725.2
NetR239_1: R239.1 TP38.1 | length 142.8
  Top Layer w6: TP38.1@26015.12,13745.57 26015.12,13702.13 26033.14,13684.11 R239.1@26107,13684.11
NetR240_2: R240.2 U3.11 | length 150
  Top Layer w6: U3.11@27562.07,13326.37 v1(27636.7,13326.37)
  Bottom Layer w6: R240.2@27589.13,13282.87 27609.87,13282.87 27636.7,13309.7 v1(27636.7,13326.37)
NetR242_2: R242.2 U1.11 | length 136
  Top Layer w6: v1(27012,13326) 27012.37,13326.37 U1.11@27079.41,13326.37
  Bottom Layer w6: v1(27012,13326) 27012,13301 27025.13,13287.87 R242.2@27050.01,13287.87
NetR243_2: R243.2 U1.10 | length 164.9
  Top Layer w6: v1(26982.87,13348.87) 26985.96,13351.96 U1.10@27079.41,13351.96
  Bottom Layer w6: v1(26982.87,13348.87) R243.2@27050.01,13348.87
NetR244_2: R244.2 U1.9 | length 119.8
  Top Layer w6: v1(27011.55,13377.55) U1.9@27079.41,13377.55
  Bottom Layer w6: v1(27011.55,13377.55) 27044,13410 R244.2@27050.01,13410
NetR245_2: R245.2 U3.10 | length 209.1
  Top Layer w6: v1(27454.03,13379.05) 27481.12,13351.96 U3.10@27562.07,13351.96
  Bottom Layer w6: v1(27454.03,13379.05) 27489.21,13343.87 R245.2@27529.28,13343.87
NetR246_2: R246.2 U3.9 | length 142.6
  Top Layer w6: v1(27487.45,13377.55) U3.9@27562.07,13377.55
  Bottom Layer w6: v1(27487.45,13377.55) 27487.2,13377.8 27487.2,13398.6 27498.6,13410 R246.2@27529.28,13410
NetR254_1: R254.1 TP36.1 | length 90.8
  Bottom Layer w6: R254.1@26605.08,12032 26635,12002.08 TP36.1@26635,11953.62
NetR259_2: R259.2 TP37.1 | length 106.3
  Bottom Layer w6: TP37.1@26540.12,12924.57 26589.2,12875.49 R259.2@26626.12,12875.49
NetTP5_1: TP5.1 U2.4 U2.5 | length 901.5
  Top Layer w6: TP5.1@26284.12,14269.57 26325.12,14228.57 26325.12,13976.57 26184.12,13835.57 26184.12,13766.57 26263.98,13686.72 26263.98,13633.02 26307.63,13589.37 26332,13589.37 ; U2.5@26359.99,13573.62 26334.38,13573.62 26332,13576 26332,13589.37 ; U2.4@26359.99,13589.37 26332,13589.37
NetTP6_1: TP6.1 U2.6 | length 965.2
  Top Layer w6: TP6.1@26149.12,14269.57 26213.12,14205.57 26258.12,14205.57 26302.12,14161.57 26302.12,13977.57 26165.12,13840.57 26165.12,13757.57 26247,13675.7 26247,13626 26315.13,13557.87 U2.6@26359.99,13557.87
NetTP7_1: TP7.1 U2.11 | length 1273.5
  Top Layer w6: v1@26251.87,13489.32 26275.18,13466 26317,13466 26330.13,13479.13 U2.11@26359.99,13479.13
  Bottom Layer w6: TP7.1@26019.12,14269.57 26086.12,14202.57 26222.12,14202.57 26301.12,14123.57 26301.12,13920.57 26323.12,13898.57 26392.12,13898.57 26405.12,13885.57 26405.12,13652.57 26319.12,13566.57 26273.12,13566.57 26252.12,13545.57 v1(26252.12,13489.57)
NetU5_R14: U5.R14 | length 583.7
  Top Layer w6: U5.R14@26663.71,12190.77 v2(26679.46,12175.03)
  ART03 w4.4: 26366.33,12091.97 26380,12105.64 26380,12183.93 26386.6,12190.53 26531.11,12190.53 26537.98,12183.66 26537.98,12165.83 26544.28,12159.53 26663.96,12159.53 v2(26679.46,12175.03)
  ART03 w5.5: v6(26352,11966) 26352,12077.63 26366.33,12091.97
OEM_RXD: P19.1 R246.1 | length 484.2
  ART04 w5.5: P19.1@27565,13020 27565,13213.45 27658.12,13306.57 27658.12,13388.74 v1(27637.6,13409.27)
  Bottom Layer w6: R246.1@27589.13,13410 v1@27637,13410
OEM_TXD: P19.2 R245.1 | length 475.2
  ART04 w5.5: P19.2@27465,13020 27465,13156.45 27596.12,13287.57 27596.12,13326.8 v1(27637.15,13367.82)
  Bottom Layer w6: R245.1@27589.13,13343.87 27613.87,13343.87 v1@27636,13366
OSC0_IN: C25.1 R17.1 U5.V10 Y2.2 | length 452.6
  Top Layer w6: Y2.2@26454.86,11747.09 26456.92,11745.03 Y2.2@26456.92,11736.62
  Top Layer w10: Y2.2@26456.92,11736.62 26511.03,11736.62 26522.74,11748.33 26522.74,11829.46 R17.1@26515.57,11836.62 26515.57,11880.04 26550.4,11914.86 26550.4,11999.3 26537.73,12011.97 U5.V10@26537.73,12096.28
OSC0_OUT: C26.1 R17.2 U5.U11 Y2.1 | length 471.2
  Top Layer w6: 26553.6,12081 26553.6,12112.16 U5.U11@26569.22,12127.78
  Top Layer w10: 26553.6,12081 26553.6,12026.1 26567,12012.7 26567,11903 26560.12,11896.12 C26.1@26560.12,11880.04 26547.86,11867.77 R17.2@26547.86,11836.62 26541.74,11830.5 26541.74,11748.93 26554.04,11736.62 Y2.1@26606.52,11736.62
OSC1_IN: C21.2 U5.A6 Y1.2 | length 278.6
  Top Layer w6: U5.A6@26411.74,12631.72 26411.74,12673.26 26387.6,12697.4 26387.6,12769 26407,12788.4 C21.2@26407,12802.11 26393,12816.11 26393,12842 26415.54,12864.54 Y1.2@26415.54,12877.11
OSC1_OUT: C22.2 U5.A4 Y1.1 | length 275.2
  Top Layer w6: U5.A4@26348.75,12631.72 26348.2,12632.27 26348.2,12672.2 26370,12694 26370,12768.2 26362,12776.2 C22.2@26362,12802.11 26381,12821.11 26381,12840 26358.46,12862.54 Y1.1@26358.46,12877.11
P_BYPASS: C4.2 U2.47 | length 155.4
  Top Layer w6: v1(26335.12,13715.57) 26340.7,13710 26393,13710 26410.19,13692.82 U2.47@26410.19,13671.06
  Bottom Layer w6: v1(26335.12,13715.57) 26337,13717.45 C4.2@26337,13764
P_INT_LDO: C3.2 U2.48 | length 180.5
  Top Layer w6: C3.2@26327,13776 26312,13761 26312,13711 26327,13696 26387,13696 26394.44,13688.56 U2.48@26394.44,13671.06
P_L1: L1.1 U2.20 | length 128.3
  Top Layer w7: 26504.67,13406 U2.20@26504.67,13428.94
  Top Layer w12: 26504.67,13406 26504.67,13377 26532.06,13349.62 L1.1@26532.06,13312
P_L2: L2.1 U2.23 | length 158.9
  Top Layer w7: 26551.92,13406 U2.23@26551.92,13428.94
  Top Layer w12: 26551.92,13406 26551.92,13379.77 26566.62,13365.07 26588.62,13365.07 26622.06,13331.64 L2.1@26622.06,13312
P_L3: L3.1 U2.31 | length 238.6
  Top Layer w7: U2.31@26602.12,13557.87 26622.66,13557.87 26674,13609.21 26674,13684.45 26686.55,13697 L3.1@26739,13697
PHY_VDDCR: C134.1 C136.1 U14.6 | length 114.7
  Top Layer w10: U14.6@27373.56,12568 v1(27373.56,12608.56)
  Bottom Layer w12: C136.1@27373.11,12534 C134.1@27373.11,12574 v1@27373.11,12608.11
PHY_XTAL1: C143.1 R141.2 R142.1 Y3.1 | length 269.7
  Top Layer w6: Y3.1@27373.11,12859 27427,12859 27438,12848 27438,12767.1 C143.1@27424.3,12753.4 27424.3,12721.7 27430.25,12715.75 R142.1@27430.25,12700.14 R141.2@27474.54,12700.14
PHY_XTAL2: R141.1 R143.1 U14.4 | length 175
  Top Layer w6: U14.4@27412.96,12568 27412.96,12615.36 27465.46,12667.86 R141.1@27474.54,12667.86 R143.1@27518.82,12667.86
PHYX: C142.1 R143.2 Y3.2 | length 249.4
  Top Layer w6: R143.2@27518.82,12700.14 27469.3,12749.67 C142.1@27469.3,12753.4 27453,12769.7 27453,12848 27464,12859 Y3.2@27522.71,12859
PMIC_INT: R1.2 U2.45 U5.B18 | length 1708.3
  Top Layer w6: v1(26377,13731) 26377,13750.4 ; R1.2@26377,13774.86 26377,13750.4 ; U2.45@26441.69,13671.06 26441.69,13693.32 26450.12,13701.76 26450.12,13713.88 26413.6,13750.4 26377,13750.4 ; U5.B18@26789.7,12600.22 v2(26805.45,12584.48)
  ART04 w5.5: v1(26377,13731) 26389.22,13743.22 26444.73,13743.22 26464.46,13723.49 26464.46,13604.34 26584.79,13484 26661.12,13484 26675.12,13470 26675.12,13440.57 26670.38,13435.82 26670.38,13390.32 26790.12,13270.57 26790.12,13246.57 26899.6,13137.1 26899.6,12752.56 26824.12,12677.09 26824.12,12603.16 v2(26805.45,12584.48)
PMIC_PGOOD: U2.26 U5.B15 U16.2 | length 1233.5
  Top Layer w6: U2.26@26602.12,13479.13 26631,13479.13 v1(26653.13,13457) 26686.55,13457 26710.55,13481 U16.2@26742.63,13481 ; U5.B15@26695.21,12600.22 26711.01,12616.02 26711.01,12669.34 26801,12759.33 v1(26801,12785.62)
  ART04 w5.5: v1(26653.13,13457) 26633.12,13437 26633.12,13260.57 26725.12,13168.57 26801.12,13168.57 26862.5,13107.2 26862.5,12847.12 v1(26801,12785.62)
PMIC_POWR_EN: U2.9 U5.C6 | length 1748.4
  Top Layer w6: v1(26282,13536) 26307.37,13510.63 U2.9@26359.99,13510.63 ; v2(26395.99,12584.47) U5.C6@26411.74,12568.72
  ART04 w5.5: v1(26282,13536) 26307.37,13510.63 26372.84,13510.63 26478.81,13404.66 26478.81,13354.89 26697.12,13136.57 26787.12,13136.57 26814.12,13109.57 26814.12,13026.57 26741.79,12954.24 26741.79,12828.25 26692.95,12779.42 26579.52,12779.42 26550.32,12808.62 26436.44,12808.62 26410.85,12783.03 26410.85,12750.27 26422.7,12738.42 26422.7,12611.18 v2(26395.99,12584.47)
PROC_A15: R18.1 U5.A15 | length 623.5
  Top Layer w6: U5.A15@26695.21,12631.72 26695.21,12672.8 26758.12,12735.72 v1(26758.12,12747.35)
  Bottom Layer w6: v1@26759.12,12748.34 v1(26758.12,12747.35) 26976.9,12747.35 26992.97,12731.27 27060.91,12731.27 27105.2,12775.56 R18.1@27105.2,12883.86
PWR_ARM: P6.1 P6.3 P6.5 R241.2 | length 5385.1
  Top Layer w60: R241.2@24810.18,13166.57 24941.12,13166.57 25154.12,13379.57 25154.12,13584.57 25507.12,13937.57 25734.12,13937.57 25794.12,13997.57 25794.12,14306.57 25859.12,14371.57 27738.12,14371.57 28044.12,14065.57 28044.12,13654.63 28350.94,13347.81 P6.1@28350.94,13170.28 P6.3@28350.94,13070.28 P6.5@28350.94,12970.28
  ART03 w5.5: v3@26906.18,14285.57 v3(26906.46,14285.86)
  ART04 w5.5: v1(26794.12,14284.57) v1@26795.12,14285.57
  other v1: 26691.12,14283.57 26741.12,14284.57 26850.12,14285.57
  other v3: 24787.12,13057.57 24843.12,13057.57 24810.12,13100.57 24810.12,13234.57 24849.02,13254.27
PWR_BUT: S3.2 S3.4 TP13.1 U2.25 | length 854.5
  Top Layer w7: U2.25@26602.12,13463.39 26617.31,13463.39 26681.12,13399.57 26817.12,13399.57 v1(26828.12,13388.57)
  Bottom Layer w7: v1(26828.12,13388.57) 26895.12,13388.57 26997.5,13490.95 S3.2@26997.5,13522.91 S3.4@26997.5,13684.33 26997.5,13722.52 26981.4,13738.62 TP13.1@26850,13738.62
PWR_LEDR: D1.1 R12.2 | length 72.2
  Top Layer w6: R12.2@25961.14,13838.62 D1.1@26033.36,13838.62
RBIAS: R144.1 U14.32 | length 154.2
  Top Layer w6: U14.32@27502.11,12537.95 27545.33,12537.95 27614.38,12607 R144.1@27627.72,12607
RCLKIN: R140.2 R142.2 U14.5 | length 147.2
  Top Layer w6: U14.5@27393.26,12568 27393.26,12628.74 27385.97,12636.03 R140.2@27385.97,12667.86 R142.2@27430.25,12667.86
REFCLKO: R118.1 R124.2 R131.2 U14.7 | length 211.7
  Top Layer w6: v1(27297.4,12636.6) R131.2@27297.4,12667.86 R124.2@27341.68,12667.86 27341.68,12635.32 27353.86,12623.14 U14.7@27353.86,12568
  Bottom Layer w6: v1(27297.4,12636.6) R118.1@27297.4,12667.86
RESET: C250.1 R203.2 U21.1 | length 655.3
  Top Layer w10: v1(25172.64,11997.64) U21.1@25229.96,11997.64
  Top Layer w15: C250.1@24864,12250 24864,12292 v1(24868.37,12296.37)
  ART04 w15: v1(24868.37,12296.37) 24903.63,12296.37 24937.92,12262.08 25036.92,12262.08 25172.64,12126.36 v1(25172.64,11997.64)
  Bottom Layer w15: R203.2@24868.37,12250 v1(24868.37,12296.37)
RI_H0: RA2.8 U21.61 | length 396
  Top Layer w6: U21.61@25365.79,12074.41 25365.79,12001.52 v1(25385.47,11981.84)
  Bottom Layer w6: RA2.8@25269.76,12204.63 25269.76,12163.24 25309,12124 25351,12124 25365.79,12109.21 25365.79,12001.52 v1(25385.47,11981.84)
RI_H1: RA2.7 U21.60 | length 297.9
  Top Layer w6: v1(25385.47,12021.21) U21.60@25385.47,12074.41
  Bottom Layer w6: RA2.7@25301.25,12204.63 25301.25,12165.75 25327,12140 25372,12140 25385.47,12126.53 v1(25385.47,12021.21)
RI_H2: RA2.6 U21.59 | length 383.9
  Top Layer w6: U21.59@25405.16,12074.41 25405.16,12001.52 v1(25424.84,11981.84)
  Bottom Layer w6: RA2.6@25332.75,12204.63 25332.75,12166.25 25345,12154 25383,12154 25405,12132 25405,12001.68 v1(25424.84,11981.84)
RI_H3: RA2.5 U21.58 | length 272.9
  Top Layer w6: v1(25424.84,12021.21) U21.58@25424.84,12074.41
  Bottom Layer w6: RA2.5@25364.24,12204.63 25364.24,12172.76 25371,12166 25390,12166 25424.84,12131.16 v1(25424.84,12021.21)
RI_H4: RA3.8 U21.57 | length 341.2
  Top Layer w6: U21.57@25444.53,12074.41 25444.53,12001.52 v1(25464.21,11981.84)
  Bottom Layer w6: RA3.8@25425.51,12206.26 25425.51,12155.49 25446,12135 25446,12000.05 v1(25464.21,11981.84)
RI_H5: RA3.7 U21.56 | length 241.2
  Top Layer w6: v1(25464.21,12021.21) U21.56@25464.21,12074.41
  Bottom Layer w6: RA3.7@25457.01,12206.26 25457.01,12148.52 25464.21,12141.32 v1(25464.21,12021.21)
RLH: R195.2 U21.7 | length 324.5
  Top Layer w6: R195.2@25008.92,12035 25068.62,12035 25082,12021.62 25082,11955 25157.47,11879.53 U21.7@25229.96,11879.53
RO_H0: RA7.1 U21.38 | length 246.7
  Top Layer w6: U21.38@25678.78,11800.79 25766.72,11800.79 25853.27,11714.24 RA7.1@25889.63,11714.24
RO_H1: RA7.2 U21.37 | length 251.6
  Top Layer w6: U21.37@25678.78,11781.1 25757.38,11781.1 25855.73,11682.75 RA7.2@25889.63,11682.75
RO_H2: RA7.3 U21.36 | length 256.5
  Top Layer w6: U21.36@25678.78,11761.42 25748.58,11761.42 25858.75,11651.25 RA7.3@25889.63,11651.25
RO_H3: RA7.4 U21.35 | length 281.4
  Top Layer w6: U21.35@25678.78,11741.73 25728.82,11741.73 25759.53,11711.02 25759.53,11676.77 25816.54,11619.76 RA7.4@25889.63,11619.76
RO_H4: RA8.1 U21.34 | length 423.5
  Top Layer w6: U21.34@25678.78,11722.05 25722.09,11722.05 25740.27,11703.87 25740.27,11592.26 25731.88,11583.87 25731.88,11353.35 RA8.1@25732.24,11352.99
RO_H5: RA8.2 U21.33 | length 424.6
  Top Layer w6: U21.33@25678.78,11702.36 25636,11702.36 25629.15,11695.51 25629.15,11517.48 25700.75,11445.87 RA8.2@25700.75,11352.99
RS232_0_RXD: P13.1 U3.13 | length 419.3
  Top Layer w6: U3.13@27562.07,13275.19 27665.19,13275.19 27711,13321 27711,13496 P13.1@27657,13550
RS232_0_TXD: P13.2 U3.14 | length 650.4
  Top Layer w6: P13.2@27557,13550 27608,13601 27696,13601 27727,13570 27727,13316 27671,13260 27620.4,13260 27610,13249.6 U3.14@27562.07,13249.6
